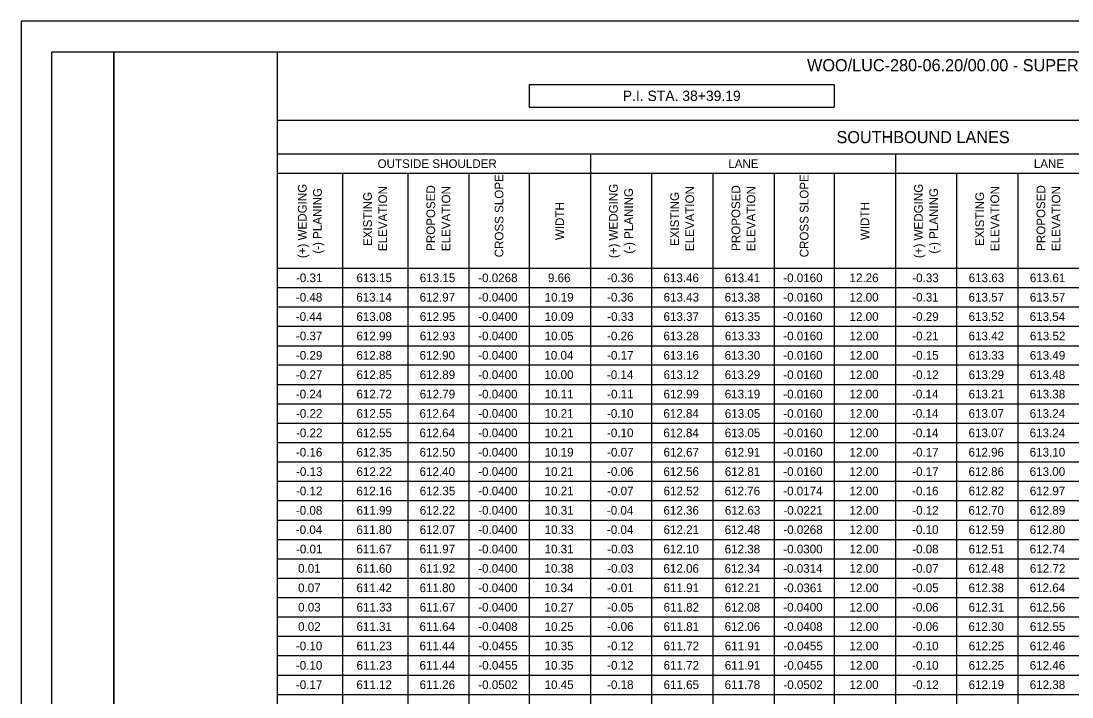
# Model space of a CAD drawing. Extents: x 0 to 34, y 0 to 22.
# Drawn here: x 0 to 16.97, y 11.08 to 22 of the extents above; entities that cross this region are included whole.
import ezdxf

# ---------------------------------------------------------------- set-up
doc = ezdxf.new("R2010")
doc.units = 0
for name, color, linetype in [('SH_Border', 7, 'Continuous'), ('SH_Cut_Line', 7, 'Continuous'), ('SH_Text', 7, 'Continuous')]:
    doc.layers.add(name, color=color, linetype=linetype)

msp = doc.modelspace()

# ---------------------------------------------------------------- linework, layer by layer
at = {"layer": 'SH_Border'}
for points in [[(0.5, 21.5), (1.5, 21.5), (1.5, 0.5), (0.5, 0.5)], [(1.5, 21.5), (33.5, 21.5), (33.5, 0.5), (1.5, 0.5)]]:
    msp.add_lwpolyline(points, close=True, dxfattribs=at)
at = {"layer": 'SH_Cut_Line'}
msp.add_lwpolyline([(0, 0), (34, 0), (34, 22), (0, 22)], close=True, dxfattribs=at)
at = {"layer": 'SH_Text'}
for p, q in [((4.135, 21.5), (4.135, 0.484)), ((5.189, 21.5), (29.368, 21.5)), ((8.203, 20.973), (13.128, 20.973)), ((8.203, 20.973), (8.203, 20.611)), ((13.128, 20.973), (13.128, 20.611)), ((8.203, 20.611), (13.128, 20.611)), ((4.135, 20.396), (29.368, 20.396)), ((4.135, 19.853), (29.368, 19.853)), ((9.191, 19.853), (9.191, 0.484)), ((14.116, 19.853), (14.116, 0.484)), ((4.135, 19.54), (24.954, 19.54)), ((5.189, 19.54), (5.189, 0.484)), ((6.243, 19.54), (6.243, 0.484)), ((7.231, 19.54), (7.231, 0.484)), ((8.203, 19.54), (8.203, 0.484)), ((10.18, 19.54), (10.18, 0.484)), ((11.168, 19.54), (11.168, 0.484)), ((12.156, 19.54), (12.156, 0.484)), ((13.128, 19.54), (13.128, 0.484)), ((15.104, 19.54), (15.104, 0.484)), ((16.093, 19.54), (16.093, 0.484)), ((4.135, 18.008), (29.368, 18.008)), ((4.135, 17.695), (29.368, 17.695)), ((4.135, 17.382), (29.368, 17.382)), ((4.135, 17.069), (29.368, 17.069)), ((4.135, 16.756), (29.368, 16.756)), ((4.135, 16.444), (29.368, 16.444)), ((4.135, 16.131), (29.368, 16.131)), ((4.135, 15.818), (29.368, 15.818)), ((4.135, 15.505), (29.368, 15.505)), ((4.135, 15.192), (29.368, 15.192)), ((4.135, 14.879), (29.368, 14.879)), ((4.135, 14.566), (29.368, 14.566)), ((4.135, 14.253), (29.368, 14.253)), ((4.135, 13.94), (29.368, 13.94)), ((4.135, 13.627), (29.368, 13.627)), ((4.135, 13.314), (29.368, 13.314)), ((4.135, 13.001), (29.368, 13.001)), ((4.135, 12.688), (29.368, 12.688)), ((4.135, 12.375), (29.368, 12.375)), ((4.135, 12.062), (29.368, 12.062)), ((4.135, 11.749), (29.368, 11.749)), ((4.135, 11.436), (29.368, 11.436)), ((4.135, 11.124), (29.368, 11.124))]:
    msp.add_line(p, q, dxfattribs=at)

# ---------------------------------------------------------------- texts
for s, height, p in [('WOO/LUC-280-06.20/00.00 - SUPERELEVATION TABLE', 0.196, (12.689, 21.188)), ('P.I. STA. 38+39.19', 0.168, (9.714, 20.708)), ('SOUTHBOUND LANES', 0.196, (13.164, 20.027)), ('OUTSIDE SHOULDER', 0.14, (5.756, 19.626)), ('LANE', 0.14, (11.417, 19.626)), ('LANE', 0.14, (16.35, 19.626)), ('-0.31', 0.14, (4.439, 17.782)), ('613.15', 0.14, (5.415, 17.782)), ('613.15', 0.14, (6.437, 17.782)), ('-0.0268', 0.14, (7.381, 17.782)), ('9.66', 0.14, (8.506, 17.782)), ('-0.36', 0.14, (9.461, 17.782)), ('613.46', 0.14, (10.371, 17.782)), ('613.41', 0.14, (11.361, 17.782)), ('-0.0160', 0.14, (12.305, 17.782)), ('12.26', 0.14, (13.375, 17.782)), ('-0.33', 0.14, (14.388, 17.782)), ('613.63', 0.14, (15.298, 17.782)), ('613.61', 0.14, (16.286, 17.782)), ('-0.48', 0.14, (4.437, 17.469)), ('613.14', 0.14, (5.412, 17.469)), ('612.97', 0.14, (6.435, 17.469)), ('-0.0400', 0.14, (7.38, 17.469)), ('10.19', 0.14, (8.452, 17.469)), ('-0.36', 0.14, (9.461, 17.469)), ('613.43', 0.14, (10.373, 17.469)), ('613.38', 0.14, (11.359, 17.469)), ('-0.0160', 0.14, (12.305, 17.469)), ('12.00', 0.14, (13.375, 17.469)), ('-0.31', 0.14, (14.387, 17.469)), ('613.57', 0.14, (15.296, 17.469)), ('613.57', 0.14, (16.285, 17.469)), ('-0.44', 0.14, (4.436, 17.156)), ('613.08', 0.14, (5.414, 17.156)), ('612.95', 0.14, (6.437, 17.156)), ('-0.0400', 0.14, (7.38, 17.156)), ('10.09', 0.14, (8.452, 17.156)), ('-0.33', 0.14, (9.463, 17.156)), ('613.37', 0.14, (10.372, 17.156)), ('613.35', 0.14, (11.361, 17.156)), ('-0.0160', 0.14, (12.305, 17.156)), ('12.00', 0.14, (13.375, 17.156)), ('-0.29', 0.14, (14.387, 17.156)), ('613.52', 0.14, (15.297, 17.156)), ('613.54', 0.14, (16.283, 17.156)), ('-0.37', 0.14, (4.438, 16.843)), ('612.99', 0.14, (5.415, 16.843)), ('612.93', 0.14, (6.437, 16.843)), ('-0.0400', 0.14, (7.38, 16.843)), ('10.05', 0.14, (8.452, 16.843)), ('-0.26', 0.14, (9.461, 16.843)), ('613.28', 0.14, (10.371, 16.843)), ('613.33', 0.14, (11.362, 16.843)), ('-0.0160', 0.14, (12.305, 16.843)), ('12.00', 0.14, (13.375, 16.843)), ('-0.21', 0.14, (14.387, 16.843)), ('613.42', 0.14, (15.297, 16.843)), ('613.52', 0.14, (16.286, 16.843)), ('-0.29', 0.14, (4.438, 16.53)), ('612.88', 0.14, (5.414, 16.53)), ('612.90', 0.14, (6.434, 16.53)), ('-0.0400', 0.14, (7.38, 16.53)), ('10.04', 0.14, (8.449, 16.53)), ('-0.17', 0.14, (9.461, 16.53)), ('613.16', 0.14, (10.371, 16.53)), ('613.30', 0.14, (11.359, 16.53)), ('-0.0160', 0.14, (12.305, 16.53)), ('12.00', 0.14, (13.375, 16.53)), ('-0.15', 0.14, (14.387, 16.53)), ('613.33', 0.14, (15.298, 16.53)), ('613.49', 0.14, (16.285, 16.53)), ('-0.27', 0.14, (4.438, 16.217)), ('612.85', 0.14, (5.415, 16.217)), ('612.89', 0.14, (6.436, 16.217)), ('-0.0400', 0.14, (7.38, 16.217)), ('10.00', 0.14, (8.45, 16.217)), ('-0.14', 0.14, (9.459, 16.217)), ('613.12', 0.14, (10.373, 16.217)), ('613.29', 0.14, (11.36, 16.217)), ('-0.0160', 0.14, (12.305, 16.217)), ('12.00', 0.14, (13.375, 16.217)), ('-0.12', 0.14, (14.387, 16.217)), ('613.29', 0.14, (15.297, 16.217)), ('613.48', 0.14, (16.284, 16.217)), ('-0.24', 0.14, (4.436, 15.904)), ('612.72', 0.14, (5.415, 15.904)), ('612.79', 0.14, (6.436, 15.904)), ('-0.0400', 0.14, (7.38, 15.904)), ('10.11', 0.14, (8.452, 15.904)), ('-0.11', 0.14, (9.462, 15.904)), ('612.99', 0.14, (10.372, 15.904)), ('613.19', 0.14, (11.36, 15.904)), ('-0.0160', 0.14, (12.305, 15.904)), ('12.00', 0.14, (13.375, 15.904)), ('-0.14', 0.14, (14.384, 15.904)), ('613.21', 0.14, (15.297, 15.904)), ('613.38', 0.14, (16.284, 15.904)), ('-0.22', 0.14, (4.439, 15.591)), ('612.55', 0.14, (5.415, 15.591)), ('612.64', 0.14, (6.433, 15.591)), ('-0.0400', 0.14, (7.38, 15.591)), ('10.21', 0.14, (8.452, 15.591)), ('-0.10', 0.14, (9.46, 15.591)), ('612.84', 0.14, (10.37, 15.591)), ('613.05', 0.14, (11.361, 15.591)), ('-0.0160', 0.14, (12.305, 15.591)), ('12.00', 0.14, (13.375, 15.591)), ('-0.14', 0.14, (14.384, 15.591)), ('613.07', 0.14, (15.296, 15.591)), ('613.24', 0.14, (16.283, 15.591)), ('-0.22', 0.14, (4.439, 15.278)), ('612.55', 0.14, (5.415, 15.278)), ('612.64', 0.14, (6.433, 15.278)), ('-0.0400', 0.14, (7.38, 15.278)), ('10.21', 0.14, (8.452, 15.278)), ('-0.10', 0.14, (9.46, 15.278)), ('612.84', 0.14, (10.37, 15.278)), ('613.05', 0.14, (11.361, 15.278)), ('-0.0160', 0.14, (12.305, 15.278)), ('12.00', 0.14, (13.375, 15.278)), ('-0.14', 0.14, (14.384, 15.278)), ('613.07', 0.14, (15.296, 15.278)), ('613.24', 0.14, (16.283, 15.278)), ('-0.16', 0.14, (4.437, 14.965)), ('612.35', 0.14, (5.415, 14.965)), ('612.50', 0.14, (6.434, 14.965)), ('-0.0400', 0.14, (7.38, 14.965)), ('10.19', 0.14, (8.452, 14.965)), ('-0.07', 0.14, (9.461, 14.965)), ('612.67', 0.14, (10.372, 14.965)), ('612.91', 0.14, (11.361, 14.965)), ('-0.0160', 0.14, (12.305, 14.965)), ('12.00', 0.14, (13.375, 14.965)), ('-0.17', 0.14, (14.386, 14.965)), ('612.96', 0.14, (15.296, 14.965)), ('613.10', 0.14, (16.283, 14.965)), ('-0.13', 0.14, (4.44, 14.652)), ('612.22', 0.14, (5.415, 14.652)), ('612.40', 0.14, (6.434, 14.652)), ('-0.0400', 0.14, (7.38, 14.652)), ('10.21', 0.14, (8.452, 14.652)), ('-0.06', 0.14, (9.461, 14.652)), ('612.56', 0.14, (10.371, 14.652)), ('612.81', 0.14, (11.361, 14.652)), ('-0.0160', 0.14, (12.305, 14.652)), ('12.00', 0.14, (13.375, 14.652)), ('-0.17', 0.14, (14.386, 14.652)), ('612.86', 0.14, (15.296, 14.652)), ('613.00', 0.14, (16.283, 14.652)), ('-0.12', 0.14, (4.439, 14.339)), ('612.16', 0.14, (5.413, 14.339)), ('612.35', 0.14, (6.437, 14.339)), ('-0.0400', 0.14, (7.38, 14.339)), ('10.21', 0.14, (8.452, 14.339)), ('-0.07', 0.14, (9.461, 14.339)), ('612.52', 0.14, (10.373, 14.339)), ('612.76', 0.14, (11.359, 14.339)), ('-0.0174', 0.14, (12.304, 14.339)), ('12.00', 0.14, (13.375, 14.339)), ('-0.16', 0.14, (14.385, 14.339)), ('612.82', 0.14, (15.297, 14.339)), ('612.97', 0.14, (16.285, 14.339)), ('-0.08', 0.14, (4.437, 14.026)), ('611.99', 0.14, (5.415, 14.026)), ('612.22', 0.14, (6.436, 14.026)), ('-0.0400', 0.14, (7.38, 14.026)), ('10.31', 0.14, (8.452, 14.026)), ('-0.04', 0.14, (9.459, 14.026)), ('612.36', 0.14, (10.371, 14.026)), ('612.63', 0.14, (11.362, 14.026)), ('-0.0221', 0.14, (12.307, 14.026)), ('12.00', 0.14, (13.375, 14.026)), ('-0.12', 0.14, (14.387, 14.026)), ('612.70', 0.14, (15.295, 14.026)), ('612.89', 0.14, (16.285, 14.026)), ('-0.04', 0.14, (4.436, 13.714)), ('611.80', 0.14, (5.413, 13.714)), ('612.07', 0.14, (6.435, 13.714)), ('-0.0400', 0.14, (7.38, 13.714)), ('10.33', 0.14, (8.453, 13.714)), ('-0.04', 0.14, (9.459, 13.714)), ('612.21', 0.14, (10.373, 13.714)), ('612.48', 0.14, (11.359, 13.714)), ('-0.0268', 0.14, (12.306, 13.714)), ('12.00', 0.14, (13.375, 13.714)), ('-0.10', 0.14, (14.385, 13.714)), ('612.59', 0.14, (15.297, 13.714)), ('612.80', 0.14, (16.283, 13.714)), ('-0.01', 0.14, (4.439, 13.401)), ('611.67', 0.14, (5.414, 13.401)), ('611.97', 0.14, (6.435, 13.401)), ('-0.0400', 0.14, (7.38, 13.401)), ('10.31', 0.14, (8.452, 13.401)), ('-0.03', 0.14, (9.463, 13.401)), ('612.10', 0.14, (10.37, 13.401)), ('612.38', 0.14, (11.359, 13.401)), ('-0.0300', 0.14, (12.305, 13.401)), ('12.00', 0.14, (13.375, 13.401)), ('-0.08', 0.14, (14.386, 13.401)), ('612.51', 0.14, (15.297, 13.401)), ('612.74', 0.14, (16.283, 13.401)), ('0.01', 0.14, (4.473, 13.088)), ('611.60', 0.14, (5.413, 13.088)), ('611.92', 0.14, (6.436, 13.088)), ('-0.0400', 0.14, (7.38, 13.088)), ('10.38', 0.14, (8.451, 13.088)), ('-0.03', 0.14, (9.463, 13.088)), ('612.06', 0.14, (10.371, 13.088)), ('612.34', 0.14, (11.358, 13.088)), ('-0.0314', 0.14, (12.304, 13.088)), ('12.00', 0.14, (13.375, 13.088)), ('-0.07', 0.14, (14.386, 13.088)), ('612.48', 0.14, (15.296, 13.088)), ('612.72', 0.14, (16.286, 13.088)), ('0.07', 0.14, (4.472, 12.775)), ('611.42', 0.14, (5.415, 12.775)), ('611.80', 0.14, (6.434, 12.775)), ('-0.0400', 0.14, (7.38, 12.775)), ('10.34', 0.14, (8.449, 12.775)), ('-0.01', 0.14, (9.462, 12.775)), ('611.91', 0.14, (10.373, 12.775)), ('612.21', 0.14, (11.361, 12.775)), ('-0.0361', 0.14, (12.307, 12.775)), ('12.00', 0.14, (13.375, 12.775)), ('-0.05', 0.14, (14.387, 12.775)), ('612.38', 0.14, (15.296, 12.775)), ('612.64', 0.14, (16.283, 12.775)), ('0.03', 0.14, (4.473, 12.462)), ('611.33', 0.14, (5.416, 12.462)), ('611.67', 0.14, (6.435, 12.462)), ('-0.0400', 0.14, (7.38, 12.462)), ('10.27', 0.14, (8.451, 12.462)), ('-0.05', 0.14, (9.463, 12.462)), ('611.82', 0.14, (10.373, 12.462)), ('612.08', 0.14, (11.359, 12.462)), ('-0.0400', 0.14, (12.305, 12.462)), ('12.00', 0.14, (13.375, 12.462)), ('-0.06', 0.14, (14.385, 12.462)), ('612.31', 0.14, (15.297, 12.462)), ('612.56', 0.14, (16.284, 12.462)), ('0.02', 0.14, (4.473, 12.149)), ('611.31', 0.14, (5.415, 12.149)), ('611.64', 0.14, (6.433, 12.149)), ('-0.0408', 0.14, (7.381, 12.149)), ('10.25', 0.14, (8.452, 12.149)), ('-0.06', 0.14, (9.461, 12.149)), ('611.81', 0.14, (10.373, 12.149)), ('612.06', 0.14, (11.359, 12.149)), ('-0.0408', 0.14, (12.306, 12.149)), ('12.00', 0.14, (13.375, 12.149)), ('-0.06', 0.14, (14.385, 12.149)), ('612.30', 0.14, (15.295, 12.149)), ('612.55', 0.14, (16.286, 12.149)), ('-0.10', 0.14, (4.437, 11.836)), ('611.23', 0.14, (5.416, 11.836)), ('611.44', 0.14, (6.433, 11.836)), ('-0.0455', 0.14, (7.383, 11.836)), ('10.35', 0.14, (8.452, 11.836)), ('-0.12', 0.14, (9.462, 11.836)), ('611.72', 0.14, (10.373, 11.836)), ('611.91', 0.14, (11.361, 11.836)), ('-0.0455', 0.14, (12.308, 11.836)), ('12.00', 0.14, (13.375, 11.836)), ('-0.10', 0.14, (14.385, 11.836)), ('612.25', 0.14, (15.298, 11.836)), ('612.46', 0.14, (16.284, 11.836)), ('-0.10', 0.14, (4.437, 11.523)), ('611.23', 0.14, (5.416, 11.523)), ('611.44', 0.14, (6.433, 11.523)), ('-0.0455', 0.14, (7.383, 11.523)), ('10.35', 0.14, (8.452, 11.523)), ('-0.12', 0.14, (9.462, 11.523)), ('611.72', 0.14, (10.373, 11.523)), ('611.91', 0.14, (11.361, 11.523)), ('-0.0455', 0.14, (12.308, 11.523)), ('12.00', 0.14, (13.375, 11.523)), ('-0.10', 0.14, (14.385, 11.523)), ('612.25', 0.14, (15.298, 11.523)), ('612.46', 0.14, (16.284, 11.523)), ('-0.17', 0.14, (4.438, 11.21)), ('611.12', 0.14, (5.415, 11.21)), ('611.26', 0.14, (6.434, 11.21)), ('-0.0502', 0.14, (7.382, 11.21)), ('10.45', 0.14, (8.452, 11.21)), ('-0.18', 0.14, (9.461, 11.21)), ('611.65', 0.14, (10.373, 11.21)), ('611.78', 0.14, (11.359, 11.21)), ('-0.0502', 0.14, (12.307, 11.21)), ('12.00', 0.14, (13.375, 11.21)), ('-0.12', 0.14, (14.387, 11.21)), ('612.19', 0.14, (15.297, 11.21)), ('612.38', 0.14, (16.284, 11.21))]:
    msp.add_text(s, height=height, dxfattribs=at).set_placement(p)
for s, p in [('CROSS SLOPE', (7.787, 18.183)), ('CROSS SLOPE', (12.712, 18.183)), ('(+) WEDGING', (4.61, 18.17)), ('(+) WEDGING', (9.633, 18.17)), ('(+) WEDGING', (14.558, 18.17)), ('(-) PLANING', (4.855, 18.242)), ('EXISTING ', (5.664, 18.365)), ('ELEVATION', (5.909, 18.283)), ('PROPOSED ', (6.685, 18.287)), ('ELEVATION', (6.93, 18.283)), ('(-) PLANING', (9.878, 18.242)), ('EXISTING ', (10.621, 18.365)), ('ELEVATION', (10.866, 18.283)), ('PROPOSED ', (11.61, 18.287)), ('ELEVATION', (11.855, 18.283)), ('(-) PLANING', (14.803, 18.242)), ('EXISTING ', (15.546, 18.365)), ('ELEVATION', (15.791, 18.283)), ('PROPOSED ', (16.534, 18.287)), ('ELEVATION', (16.779, 18.283)), ('WIDTH', (8.767, 18.461)), ('WIDTH', (13.692, 18.461))]:
    msp.add_text(s, height=0.14, rotation=90, dxfattribs=at).set_placement(p)

doc.saveas('drawing.dxf')
